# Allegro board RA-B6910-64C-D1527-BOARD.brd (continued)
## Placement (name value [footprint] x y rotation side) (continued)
R573  3.3K_1%  [R0402]  135.05 135.31 0 bottom
R574  X  [R0402]  161.21 109.25 180 top
R575  3.3K_1%  [R0402]  161.21 108.23 0 top
R576  X  [R0402]  157.4 105.84 90 top
R577  3.3K_1%  [R0402]  158.42 105.84 270 top
R578  3.3K_1%  [R0402]  152.07 105.84 90 bottom
R579  X  [R0402]  153.08 105.84 270 bottom
R580  X  [R0402]  161.21 118.16 180 top
R581  3.3K_1%  [R0402]  150.03 105.84 90 bottom
R582  X  [R0402]  149.02 105.84 270 bottom
R583  X  [R0402]  133.9 130.99 0 bottom
R584  3.3K_1%  [R0402]  154.35 105.84 90 top
R585  X  [R0402]  155.37 105.84 270 top
R586  3.3K_1%  [R0402]  146.99 105.84 90 bottom
R587  X  [R0402]  145.97 105.84 270 bottom
R588  3.3K_1%  [R0402]  161.21 110.26 180 top
R589  X  [R0402]  161.21 111.28 0 top
R590  X  [R0402]  158.67 108.51 180 bottom
R591  3.3K_1%  [R0402]  158.67 109.53 0 bottom
R592  0  [R0402]  155.11 108.76 270 bottom
R593  X  [R0402]  154.1 108.76 90 bottom
R594  X  [R0402]  176.96 106.86 90 bottom
R595  10K_1%  [R0402]  169.85 106.86 270 bottom
R596  0  [R0402]  175.94 106.86 270 bottom
R597  10K_1%  [R0402]  167.81 106.86 270 bottom
R598  10K_1%  [R0402]  172.89 106.86 90 bottom
R599  10K_1%  [R0402]  174.93 106.86 270 bottom
R600  100K_1%  [R0402]  164.77 106.86 270 top
R601  100K_1%  [R0402]  158.67 110.54 180 bottom
R602  X  [R0402]  158.67 111.56 0 bottom
R603  X  [R0402]  176.45 109.4 180 bottom
R604  X  [R0402]  176.45 110.41 180 bottom
R605  X  [R0402]  173.27 111.18 0 top
R606  X  [R0402]  172.64 113.21 270 top
R607  3.3K_1%  [R0402]  165.15 88.06 0 top
R608  3.3K_1%  [R0402]  154.48 87.05 0 top
R609  X  [R0402]  154.48 88.06 0 top
R610  15K_1%  [R0402]  165.15 87.05 0 top
R611  1.5K_1%  [R0402]  165.15 86.03 0 top
R612  33_1%  [R0402]  173.91 106.86 90 bottom
R613  33_1%  [R0402]  170.86 106.86 90 bottom
R614  33_1%  [R0402]  168.83 106.86 90 bottom
R615  22  [R0402]  170.35 121.34 270 top
R616  33  [R0402]  163.75 106.86 270 bottom
R617  4.99K_1%  [R0402]  172.64 121.34 270 bottom
R618  33  [R0402]  164.77 106.86 270 bottom
R619  33  [R0402]  165.78 106.86 270 bottom
R620  33  [R0402]  166.8 106.86 270 bottom
R621  3.3K_1%  [R0402]  171.88 106.86 270 bottom
R622  3.3K_1%  [R0402]  164.89 115.62 0 top
R623  3.3K_1%  [R0402]  164.77 110.67 0 top
R624  3.3K_1%  [R0402]  164.77 109.65 0 top
R625  3.3K_1%  [R0402]  168.96 121.34 90 bottom
R626  3.3K_1%  [R0402]  169.97 121.34 90 bottom
R627  10K_1%  [R0402]  164.89 114.48 0 top
R628  4.7K  [R0402]  176.45 108.38 0 bottom
R629  0  [R0603]  159.81 118.29 180 bottom
R630  3.09K_1%  [R0402]  161.21 114.61 0 top
R631  49.9K_1%  [R0603]  161.59 116.89 180 top
R632  15K_1%  [R0402]  161.21 115.62 180 top
R641  0  [R0402]  117.01 26.47 0 top
R642  3.3  [R0402]  127.43 19.86 0 top
R643  0  [R0402]  127.43 20.88 0 top
R644  1_1%  [R0402]  127.43 20.88 0 bottom
R645  499K_1%  [R0603]  116.63 23.42 270 top
R646  150K_1%  [R0603]  117.01 16.18 270 top
R647  0  [R0402]  118.28 16.31 270 top
R648  0  [R0402]  119.43 16.31 270 top
R649  12.7K_1%  [R0603]  120.82 12.75 90 top
R650  1_1%  [R0402]  123.11 13.89 90 top
R651  10K_1%  [R0402]  127.43 21.9 0 bottom
R652  10K_1%  [R0402]  119.55 13.13 90 top
R653  10K_1%  [R0402]  127.43 27.61 0 top
R654  10K_1%  [R0402]  124.38 13.89 270 top
R656  0  [R0402]  127.43 26.59 0 top
R657  200_1%  [R0402]  127.43 18.85 180 top
R658  0  [R0402]  127.43 22.91 0 top
R659  0  [R0402]  127.43 24.18 0 top
R660  0  [R0402]  127.43 25.32 0 top
R662  40.2_1%  [R0402]  66.34 17.83 180 bottom
R663  X  [R0402]  66.34 19.86 0 bottom
R664  120_1%  [R0402]  66.34 18.85 180 bottom
R665  2  [R0603]  113.2 23.83 270 top
R666  0  [R0402]  111.04 13.26 270 top
R667  1  [R0805]  105.08 16.23 270 top
R668  150K_1%  [R0603]  114.6 23.83 270 top
R669  0  [R0402]  115.11 13.26 270 top
R670  0  [R0402]  113.08 13.26 90 top
R671  X  [R0402]  114.09 13.26 270 top
R672  2  [R0603]  102.15 23.55 270 top
R673  0  [R0402]  99.61 13.26 270 top
R674  1  [R0805]  93.01 16.99 270 top
R675  150K_1%  [R0603]  103.55 23.55 270 top
R676  0  [R0402]  103.17 13.26 270 top
R677  0  [R0402]  101.65 13.26 90 top
R678  1  [R0805]  127.43 15.29 0 top
R679  0  [R0402]  133.4 13.77 270 top
R680  2  [R0603]  138.1 14.66 270 top
R681  150K_1%  [R0603]  135.17 21.51 0 bottom
R682  0  [R0402]  134.41 13.77 90 top
R683  X  [R0402]  135.43 13.77 90 top
R684  0  [R0402]  136.44 13.77 270 top
R685  0  [R0402]  162.99 38.28 180 top
R686  0  [R0402]  162.99 33.71 180 top
R687  3.3  [R0402]  174.29 32.44 0 top
R688  0  [R0402]  174.29 33.45 0 top
R689  1_1%  [R0402]  174.29 35.48 0 top
R690  X  [R0402]  162.99 32.69 0 top
R691  49.9K_1%  [R0603]  162.99 31.42 0 top
R692  20K_1%  [R0603]  162.99 30.02 180 top
R693  0  [R0402]  165.15 29.9 270 top
R694  0  [R0402]  166.67 29.9 270 top
R695  12.7K_1%  [R0603]  168.07 26.34 90 top
R696  1_1%  [R0402]  170.48 27.48 90 top
R697  10K_1%  [R0402]  174.29 35.48 0 bottom
R698  10K_1%  [R0402]  166.67 26.72 90 top
R699  X  [R0402]  174.29 40.69 0 top
R700  10K_1%  [R0402]  172.77 29.9 270 top
R702  200_1%  [R0402]  174.29 31.42 180 top
R703  0  [R0402]  174.29 39.68 0 top
R704  0  [R0402]  174.29 36.5 0 top
R705  0  [R0402]  174.29 37.52 0 top
R706  0  [R0402]  174.29 38.66 0 top
R708  1  [R0805]  154.48 36.37 0 top
R709  0  [R0402]  159.3 40.18 0 top
R710  2  [R0603]  153.97 34.47 0 bottom
R711  150K_1%  [R0603]  151.43 45.01 90 bottom
R712  0  [R0402]  159.3 42.22 180 bottom
R713  X  [R0402]  159.3 42.22 180 top
R714  0  [R0402]  159.3 43.87 0 top
R715  1  [R0805]  154.35 45.85 0 top
R716  0  [R0402]  161.34 49.96 0 top
R717  2  [R0603]  146.1 53.01 180 bottom
R718  150K_1%  [R0603]  152.45 49.45 270 bottom
R719  0  [R0402]  159.18 51.11 180 top
R720  X  [R0402]  159.18 52.12 180 top
R721  0  [R0402]  159.18 53.14 0 top
R722  0  [R0402]  56.05 25.96 180 top
R723  3.3  [R0402]  66.34 18.85 0 top
R724  0  [R0402]  66.34 19.86 0 top
R725  1_1%  [R0402]  66.34 21.9 0 top
R726  0  [R0402]  55.67 20.37 0 top
R727  27K_1%  [R0402]  55.67 18.09 0 top
R728  X  [R0402]  55.67 19.1 0 top
R729  37.4K_1%  [R0603]  55.29 16.69 180 top
R730  0  [R0402]  57.32 16.82 270 top
R731  0  [R0402]  58.47 16.82 270 top
R732  12.7K_1%  [R0603]  59.74 15.93 90 bottom
R733  1_1%  [R0402]  62.02 13.89 90 top
R734  10K_1%  [R0402]  66.34 21.9 0 bottom
R735  10K_1%  [R0402]  58.47 14.28 90 top
R736  X  [R0402]  66.34 27.36 0 top
R737  10K_1%  [R0402]  64.56 13.89 270 top
R739  0  [R0402]  66.34 26.34 0 top
R740  200_1%  [R0402]  66.34 17.83 180 top
R741  0  [R0402]  66.34 22.91 0 top
R742  0  [R0402]  66.34 24.18 0 top
R743  0  [R0402]  66.34 25.32 0 top
R745  2  [R0603]  90.09 23.55 270 top
R746  0  [R0402]  87.04 13.26 270 top
R748  1  [R0805]  80.82 16.36 270 top
R749  150K_1%  [R0603]  91.49 23.55 270 top
R750  0  [R0402]  91.11 13.26 270 top
R751  0  [R0402]  89.07 13.26 90 top
R752  X  [R0402]  90.09 13.26 270 top
R753  1  [R0805]  70.53 21.13 270 top
R754  0  [R0402]  74.85 13.77 270 top
R755  2  [R0603]  78.66 23.04 90 top
R756  150K_1%  [R0603]  80.06 23.04 90 top
R757  0  [R0402]  76.88 13.77 90 top
R758  X  [R0402]  77.9 13.77 90 top
R759  0  [R0402]  78.91 13.77 270 top
R760  4.7K  [R0402]  117.65 136.07 0 top
R761  4.7K  [R0402]  113.33 127.56 270 bottom
R762  4.7K  [R0402]  102.41 132.77 180 top
R763  33  [R0402]  112.31 127.56 90 bottom
R764  X  [R0402]  110.28 127.56 270 bottom
R765  33  [R0402]  117.65 134.04 180 top
R766  33  [R0402]  102.41 131.75 180 top
R767  33  [R0402]  117.65 135.05 180 top
R768  33  [R0402]  102.41 134.8 180 top
R769  33  [R0402]  102.41 135.81 180 top
R770  4.7K  [R0402]  117.27 145.47 0 top
R771  4.7K  [R0402]  117.27 143.43 0 top
R772  4.7K  [R0402]  101.9 144.45 180 top
R773  33  [R0402]  117.27 142.42 180 top
R774  33  [R0402]  117.27 144.45 180 top
R775  X  [R0402]  101.9 141.4 0 top
R776  33  [R0402]  101.9 143.43 180 top
R777  33  [R0402]  117.27 146.48 180 top
R778  33  [R0402]  101.9 145.72 180 top
R779  33  [R0402]  101.9 146.74 180 top
R780  X  [R0402]  105.46 54.66 90 top
R781  49.9_1%  [R0402]  113.71 58.6 180 top
R782  1K_1%  [R0402]  103.68 71.43 180 bottom
R783  X  [R0402]  113.71 61.65 180 top
R784  5.11K_1%  [R0402]  106.47 54.66 90 top
R785  5.11K_1%  [R0402]  104.44 54.66 90 top
R786  5.11K_1%  [R0402]  104.44 54.66 90 bottom
R787  5.11K_1%  [R0402]  99.87 66.29 0 bottom
R788  10  [R0402]  94.03 57.07 90 bottom
R789  10  [R0402]  94.79 54.66 90 top
R790  X  [R0402]  110.54 54.66 90 top
R791  10  [R0402]  95.8 54.66 90 top
R792  10K_1%  [R0402]  107.49 54.66 90 top
R793  10K_1%  [R0402]  108.5 54.66 90 top
R794  10K_1%  [R0402]  98.98 63.68 180 bottom
R795  5.11K_1%  [R0402]  102.41 54.66 90 top
R796  5.11K_1%  [R0402]  109.52 54.66 90 bottom
R797  5.11K_1%  [R0402]  108.5 54.66 90 bottom
R798  5.11K_1%  [R0402]  113.71 56.57 180 top
R799  5.11K_1%  [R0402]  111.55 54.66 90 bottom
R800  X  [R0402]  111.55 57.07 90 bottom
R801  X  [R0402]  113.71 57.58 180 top
R802  4.7K  [R0402]  150.8 65.71 90 bottom
R803  33  [R0402]  149.78 65.71 90 bottom
R804  33  [R0402]  148.76 65.71 90 bottom
R805  4.7K  [R0402]  149.78 76.38 90 bottom
R806  4.7K  [R0402]  147.75 65.71 90 bottom
R807  33  [R0402]  144.95 76.12 180 bottom
R808  33  [R0402]  144.95 75.11 180 bottom
R809  7.5K  [R0603]  86.89 84.51 90 bottom
R810  22.6_1%  [R0603]  104.31 114.1 0 top
R811  0  [R0402]  103.81 110.54 0 top
R812  0  [R0402]  103.81 109.53 0 top
R813  0  [R0402]  103.81 105.46 0 bottom
R814  0  [R0402]  103.81 115.62 0 top
R815  0  [R0402]  102.15 103.81 90 top
R816  5.11K_1%  [R0402]  81.45 108.76 270 top
R817  5.11K_1%  [R0402]  82.47 105.59 270 bottom
R818  5.11K_1%  [R0402]  92.63 116.26 270 top
R819  5.11K_1%  [R0402]  103.81 108.51 180 top
R820  X  [R0402]  82.34 116.13 270 top
R821  5.11K_1%  [R0402]  84.5 105.59 270 bottom
R822  5.11K_1%  [R0402]  86.53 111.18 270 bottom
R823  5.11K_1%  [R0402]  84.5 111.18 270 bottom
R824  5.11K_1%  [R0402]  105.84 105.97 180 bottom
R825  X  [R0402]  103.81 116.64 0 top
R826  X  [R0402]  103.17 104.95 270 top
R827  5.11K_1%  [R0402]  103.81 108.51 180 bottom
R828  X  [R0402]  114.09 71.93 0 bottom
R829  0  [R0402]  81.45 108.76 270 bottom
R830  5.11K_1%  [R0402]  91.36 82.22 90 bottom
R831  5.11K_1%  [R0402]  89.33 82.22 90 bottom
R832  5.11K_1%  [R0402]  90.6 112.95 270 top
R833  5.11K_1%  [R0402]  88.57 112.95 270 top
R834  5.11K_1%  [R0402]  90.34 82.22 90 bottom
R835  49.9_1%  [R0402]  102.92 56.57 180 top
R836  5.11K_1%  [R0402]  103.81 111.56 180 bottom
R837  X  [R0402]  103.42 54.66 90 bottom
R838  5.11K_1%  [R0402]  103.81 109.53 180 bottom
R839  33  [R0402]  82.98 112.95 270 bottom
R840  2.2K  [R0402]  93.14 81.71 180 bottom
R841  0  [R0402]  91.61 112.95 90 top
R842  5.11K_1%  [R0402]  78.79 108.76 270 bottom
R843  5.11K_1%  [R0402]  100.38 54.66 90 top
R844  5.11K_1%  [R0402]  79.8 108.76 90 bottom
R845  5.11K_1%  [R0402]  103.42 54.66 90 top
R846  7.5K  [R0603]  100.76 90.35 0 bottom
R847  5.11K_1%  [R0402]  80.44 112.95 270 bottom
R848  5.11K_1%  [R0402]  81.2 116.13 270 top
R849  33  [R0402]  113.71 54.53 0 top
R850  5.11K_1%  [R0402]  81.45 112.95 270 bottom
R851  5.11K_1%  [R0402]  81.45 105.59 270 bottom
R852  33  [R0402]  91.99 116.38 90 bottom
R853  33  [R0402]  94.03 116.38 90 bottom
R854  5.11K_1%  [R0402]  91.61 116.26 270 top
R855  5.11K_1%  [R0402]  89.58 112.95 270 top
R856  5.11K_1%  [R0402]  84.25 113.59 270 bottom
R857  5.11K_1%  [R0402]  103.81 107.49 180 bottom
R858  5.11K_1%  [R0402]  83.49 116.13 270 top
R859  5.11K_1%  [R0402]  82.47 112.95 270 top
R860  X  [R0402]  141.27 112.19 0 bottom
R861  5.11K_1%  [R0402]  89.58 112.95 270 bottom
R862  10K_1%  [R0402]  102.66 89.08 180 bottom
R863  0  [R0402]  136.95 111.56 180 bottom
R864  5.11K_1%  [R0402]  84.5 105.59 270 top
R865  5.11K_1%  [R0402]  83.49 105.59 270 top
R866  X  [R0402]  80.44 112.95 270 top
R867  X  [R0402]  138.48 108.26 0 bottom
R868  1K  [R0402]  103.81 113.97 180 bottom
R869  0  [R0402]  136.32 108.26 180 bottom
R870  5.11K_1%  [R0402]  88.95 116.26 270 bottom
R871  1K  [R0402]  91.99 108.76 270 top
R872  X  [R0402]  139.11 112.95 0 bottom
R873  10K_1%  [R0402]  93.77 108.76 270 bottom
R874  5.11K_1%  [R0402]  103.81 110.54 180 bottom
R875  0  [R0402]  136.95 112.95 180 bottom
R876  5.11K_1%  [R0402]  92.63 105.59 270 top
R877  5.11K_1%  [R0402]  90.6 112.95 270 bottom
R878  X  [R0402]  138.48 109.65 0 bottom
R879  10K_1%  [R0402]  90.6 108.76 270 bottom
R880  5.11K_1%  [R0402]  103.81 112.88 180 bottom
R881  0  [R0402]  136.32 109.65 180 bottom
R882  5.11K_1%  [R0402]  91.61 108.76 270 bottom
R883  10K_1%  [R0402]  87.55 108.76 270 bottom
R884  5.11K_1%  [R0402]  85.52 108.76 270 bottom
R885  5.11K_1%  [R0402]  84.5 108.76 270 bottom
R886  5.11K_1%  [R0402]  93.01 116.38 270 bottom
R887  X  [R0402]  86.53 108.76 90 bottom
R888  1K  [R0402]  93.77 108.76 270 top
R889  X  [R0402]  83.49 108.76 90 bottom
R890  1M_1%  [R0603]  104.44 105.46 270 top
R891  5.11K_1%  [R0402]  103.81 111.56 180 top
R892  5.11K_1%  [R0402]  103.81 107.49 180 top
R893  2.2K  [R0402]  95.68 119.56 90 top
R894  1M_1%  [R0603]  97.58 105.59 180 top
R895  5.11K_1%  [R0402]  85.26 83.11 90 bottom
R896  5.11K_1%  [R0402]  103.42 57.07 90 bottom
R897  1K  [R0402]  96.69 119.56 270 top
R898  5.11K_1%  [R0402]  79.68 115.25 270 top
R899  5.11K_1%  [R0402]  93.77 112.95 270 bottom
R900  5.11K_1%  [R0402]  94.28 96.44 270 bottom
R901  5.11K_1%  [R0402]  81.33 97.21 270 bottom
R902  X  [R0402]  101.39 54.66 90 top
R903  X  [R0402]  81.45 112.95 270 top
R904  X  [R0402]  89.96 116.26 270 bottom
R905  0  [R0402]  116.63 55.55 0 top
R906  X  [R0402]  116.63 54.53 0 top
R907  X  [R0402]  101.39 54.66 90 bottom
R908  49.9_1%  [R0402]  97.33 54.66 270 bottom
R909  X  [R0402]  99.36 54.66 90 bottom
R910  120_1%  [R0402]  98.34 54.66 90 bottom
R911  5.11K_1%  [R0402]  92.25 69.27 270 bottom
R912  5.11K_1%  [R0402]  93.26 69.27 270 bottom
R913  5.11K_1%  [R0402]  96.31 54.66 90 bottom
R914  240_1%  [R0402]  91.36 67.23 270 bottom
R915  240_1%  [R0402]  95.04 57.07 90 bottom
R916  0  [R0402]  98.34 57.07 270 bottom
R917  1K  [R0402]  100.38 54.66 90 bottom
R918  220_1%  [R0402]  97.33 57.07 270 bottom
R919  0  [R0402]  99.36 57.07 270 bottom
R920  5.11K_1%  [R0402]  100.88 57.07 90 bottom
R921  5.11K_1%  [R0402]  106.99 63.04 180 bottom
R922  5.11K_1%  [R0402]  97.33 54.66 90 top
R923  10K_1%  [R0402]  97.33 79.18 270 bottom
R924  10K_1%  [R0402]  96.19 79.18 270 bottom
R925  10K_1%  [R0402]  104.19 102.29 0 top
R926  150_1%  [R0402]  113.71 64.69 180 top
R927  10K_1%  [R0402]  107.36 80.95 0 bottom
R928  10K_1%  [R0402]  107.36 81.97 0 bottom
R929  10K_1%  [R0402]  104.19 103.3 0 top
R930  75_1%  [R0402]  113.71 63.68 0 top
R931  10K_1%  [R0402]  88.31 82.22 270 bottom
R932  10K_1%  [R0402]  87.3 81.46 270 bottom
R933  10K_1%  [R0402]  105.08 91.87 0 bottom
R934  0  [R0402]  107.87 115.75 0 top
R935  0  [R0402]  103.81 115.62 0 bottom
R936  5.11K_1%  [R0402]  107.87 114.73 0 top
R937  5.11K_1%  [R0402]  103.81 116.64 0 bottom
R938  22  [R0402]  100.5 101.78 0 bottom
R939  1M_1%  [R0603]  108 103.18 0 top
R940  33  [R0402]  118.03 125.53 180 top
R941  4.7K  [R0402]  118.03 126.8 0 top
R942  33  [R0402]  129.21 126.54 0 top
R943  33  [R0402]  129.21 127.56 0 top
R944  33  [R0402]  129.21 128.58 0 top
R945  5.11K_1%  [R0402]  85.52 105.59 270 bottom
R946  5.11K_1%  [R0402]  94.03 57.07 270 top
R947  5.11K_1%  [R0402]  114.09 73.97 0 top
R948  5.11K_1%  [R0402]  113.71 59.61 0 top
R949  5.11K_1%  [R0402]  113.71 60.63 0 top
R950  5.11K_1%  [R0402]  97.71 69.9 90 bottom
R951  5.11K_1%  [R0402]  95.8 69.01 90 bottom
R952  5.11K_1%  [R0402]  94.79 69.01 90 bottom
R953  5.11K_1%  [R0402]  113.71 62.66 0 top
R954  49.9_1%  [R0402]  98.73 70.79 90 bottom
R955  5.11K_1%  [R0402]  114.09 71.93 0 top
R956  5.11K_1%  [R0402]  114.09 72.95 0 top
R957  X  [R0402]  91.87 63.55 0 bottom
R958  5.11K_1%  [R0402]  103.81 112.88 180 top
R959  7.50K_1%  [R0805]  102.03 81.59 270 bottom
R960  8.2K  [R0402]  105.13 92.89 0 bottom
R961  49.9_1%  [R0402]  113.71 55.55 180 top
R962  49.9_1%  [R0402]  100 62.54 180 bottom
R963  10K_1%  [R0402]  106.47 54.66 270 bottom
R964  49.9_1%  [R0402]  74.72 62.79 270 bottom
R965  10K_1%  [R0402]  105.46 54.66 270 bottom
R966  49.9_1%  [R0402]  73.2 62.79 90 bottom
R967  130_1%  [R0603]  81.71 72.82 90 bottom
R968  40.2_1%  [R0402]  80.95 74.85 180 bottom
R969  120_1%  [R0402]  81.45 77.39 0 bottom
R970  1_1%  [R0402]  81.45 75.87 180 bottom
R971  7.5K  [R0603]  101.27 85.27 0 bottom
R972  10K_1%  [R0402]  83.49 108.76 270 top
R973  0  [R0402]  88.57 105.59 270 top
R974  10K_1%  [R0402]  85.52 108.76 270 top
R975  5.11K_1%  [R0402]  84.5 108.76 270 top
R976  1K  [R0402]  86.53 108.76 270 top
R977  5.11K_1%  [R0402]  82.47 105.59 270 top
R978  5.11K_1%  [R0402]  82.47 108.76 270 top
R979  1K  [R0402]  87.55 113 270 bottom
R980  1K  [R0402]  88.57 112.95 270 bottom
R981  1K  [R0402]  89.58 105.59 270 bottom
R982  X  [R0402]  87.93 108.76 270 top
R983  10K_1%  [R0402]  89.96 108.76 270 top
R984  10K_1%  [R0402]  89.58 105.59 270 top
R985  1K_1%  [R0402]  57.96 68.12 270 bottom
R986  10K_1%  [R0402]  87.55 113 270 top
R987  10K_1%  [R0402]  91.61 105.59 270 top
R988  10K_1%  [R0402]  88.95 108.76 270 top
R989  10K_1%  [R0402]  90.6 105.59 270 top
R990  10K_1%  [R0402]  90.98 108.76 270 top
R991  0  [R0402]  59.74 66.47 180 bottom
R992  49.9_1%  [R0402]  86.15 112.95 90 top
R993  1K_1%  [R0402]  59.74 67.62 0 bottom
R994  49.9_1%  [R0402]  86.53 105.59 90 top
R995  49.9_1%  [R0402]  87.55 105.59 90 top
R996  49.9_1%  [R0402]  85.52 105.59 90 top
R997  X  [R0402]  107.11 117.4 180 bottom
R998  4.7K  [R0402]  107.11 120.45 180 bottom
R999  4.7K  [R0402]  107.11 121.46 180 bottom
R1000  4.7K  [R0402]  99.49 118.92 180 top
R1001  4.7K  [R0402]  107.11 118.42 180 bottom
R1002  X  [R0402]  107.11 119.43 180 bottom
R1003  0  [R0402]  99.49 119.94 180 top
R1004  X  [R0402]  107.11 122.48 180 bottom
R1005  33  [R0402]  99.49 121.97 180 top
R1006  33  [R0402]  99.49 122.99 180 top
R1007  X  [R0402]  99.49 120.96 0 top
R1008  0  [R1206]  112.19 83.62 0 bottom
R1018  49.9_1%  [R0402]  109.27 57.58 180 top
R1019  49.9_1%  [R0402]  109.52 54.66 90 top
R1020  49.9_1%  [R0402]  111.55 54.66 90 top
R1023  931_1%  [R0402]  105.72 59.87 180 bottom
R1025  49.9_1%  [R0402]  103.3 63.55 180 bottom
R1028  1K  [R0402]  74.09 125.65 270 top
R1029  150  [R0402]  102.66 59.99 90 bottom
R1030  1K  [R0402]  101.9 140.39 0 top
R1031  1K  [R0402]  111.17 107.11 0 bottom
R1032  1K  [R0402]  102.41 133.78 0 top
R1033  1K  [R0402]  113.97 139.5 0 bottom
R1034  1K  [R0402]  113.97 140.51 0 bottom
R1035  1K  [R0402]  99.36 54.66 270 top
R1036  1K  [R0402]  122.86 111.18 0 bottom
R1037  240_1%  [R0402]  113.84 136.07 0 bottom
R1039  49.9_1%  [R0402]  113.84 130.99 0 bottom
R1040  0  [R0402]  113.97 138.48 180 bottom
R1041  0  [R0402]  122.86 110.16 180 bottom
R1042  0  [R0402]  122.86 106.1 180 bottom
R1043  0  [R0402]  113.97 141.53 180 bottom
R1045  0  [R0402]  122.86 109.14 180 bottom
R1046  0  [R0402]  113.97 142.55 180 bottom
R1047  0  [R0402]  113.84 134.04 180 bottom
R1048  X  [R0402]  113.97 144.58 180 bottom
R1049  0  [R0402]  113.84 135.05 180 bottom
R1050  0  [R0402]  113.84 132 180 bottom
R1051  1K  [R0402]  113.97 143.56 180 bottom
R1052  1K  [R0402]  122.86 107.11 180 bottom
R1053  4.7K  [R0402]  122.86 108.13 0 bottom
R1054  240_1%  [R0402]  122.86 104.06 0 top
R1055  240_1%  [R0402]  122.86 100 0 top
R1056  X  [R0402]  122.73 97.71 0 top
R1057  1K  [R0402]  111.17 109.91 0 top
R1058  240_1%  [R0402]  122.86 101.02 0 top
R1059  0  [R0402]  122.86 103.05 180 top
R1060  0  [R0402]  122.86 102.03 180 top
R1061  0  [R0402]  122.86 98.73 180 top
R1062  0  [R0402]  122.73 96.7 180 top
R1063  49.9_1%  [R0402]  122.86 105.08 0 top
R1064  0  [R0402]  122.86 109.14 180 top
R1065  1K  [R0402]  111.17 102.54 0 top
R1066  1K  [R0402]  134.41 66.85 0 top
R1068  0  [R0402]  125.78 70.79 180 top
R1069  0  [R0402]  125.78 72.82 180 top
R1070  0  [R0402]  122.86 108.13 180 top
R1071  0  [R0402]  122.86 106.1 180 top
R1072  1K  [R0402]  125.78 69.77 180 top
R1073  1K  [R0402]  125.78 71.81 180 top
R1074  1K  [R0402]  125.78 73.84 180 top
R1075  1K  [R0402]  125.78 74.85 180 top
R1076  5.11K_1%  [R0402]  98.34 54.66 90 top
R1077  5.11K_1%  [R0402]  122.86 110.16 180 top
R1078  1K  [R0402]  122.86 107.11 180 top
R1079  X  [R0402]  125.78 70.79 0 bottom
R1080  X  [R0402]  125.78 72.82 0 bottom
R1081  1K  [R0402]  137.33 70.16 180 bottom
R1082  1K  [R0402]  137.33 71.17 180 bottom
R1083  X  [R0402]  125.78 73.84 180 bottom
R1084  200K  [R0603]  137.71 68.89 0 bottom
R1085  X  [R0402]  125.78 71.81 180 bottom
R1086  X  [R0402]  125.78 74.85 180 bottom
R1087  10K_1%  [R0402]  137.33 72.19 0 bottom
R1088  10  [R0402]  137.33 73.2 0 bottom
R1089  10  [R0402]  137.33 75.24 0 bottom
R1090  10  [R0402]  137.33 74.22 0 bottom
R1091  240_1%  [R0402]  74.34 38.66 180 top
R1092  240_1%  [R0402]  74.34 37.52 180 top
R1093  4.7K  [R0402]  64.18 36.12 0 top
R1094  4.7K  [R0402]  64.18 37.14 0 top
R1095  10K_1%  [R0402]  64.18 38.15 0 top
R1096  1K  [R0402]  125.01 65.71 270 top
R1097  4.7K  [R0402]  137.46 105.33 180 top
R1098  4.7K  [R0402]  137.46 104.32 180 top
R1099  240_1%  [R0402]  126.28 103.81 0 top
R1100  240_1%  [R0402]  126.28 104.83 0 top
R1101  240_1%  [R0402]  129.08 110.41 90 top
R1102  240_1%  [R0402]  128.06 110.41 90 top
R1103  10K_1%  [R0402]  128.95 122.1 270 top
R1104  10K_1%  [R0402]  137.46 103.3 180 top
R1105  1K  [R0402]  145.21 65.71 270 top
R1106  1K  [R0402]  145.21 77.39 270 top
R1107  0  [R0402]  144.19 65.71 90 top
R1108  1K  [R0402]  152.19 76.38 270 bottom
R1109  0  [R0402]  143.18 65.71 90 top
R1110  0  [R0402]  142.16 65.71 90 top
R1111  33  [R0402]  148.76 65.71 90 top
R1112  0  [R0402]  150.8 65.71 90 top
R1113  1K  [R0402]  147.75 65.71 90 top
R1114  1K  [R0402]  149.78 65.71 90 top
R1115  0  [R0402]  122.09 16.31 90 top
R1116  X  [R0402]  18.21 41.07 270 bottom
R1118  X  [R0402]  19.35 41.07 270 bottom
R1120  X  [R0402]  10.21 71.68 90 bottom
R1122  X  [R0402]  25.83 50.47 180 bottom
R1123  0  [R0402]  22.91 47.93 90 bottom
R1125  0  [R0402]  24.3 67.23 180 bottom
R1129  0  [R0402]  122.22 113.97 180 top
R1130  0  [R0402]  122.22 114.99 180 top
R1131  0  [R0402]  91.23 133.02 0 bottom
R1132  0  [R0402]  125.01 110.41 90 bottom
R1133  0  [R0402]  124.76 121.08 180 top
R1134  X  [R0402]  96.31 57.07 90 bottom
R1135  X  [R0402]  84.37 147.5 90 bottom
R1136  X  [R0402]  85.39 147.5 90 bottom
R1137  240_1%  [R0402]  113.84 133.02 0 bottom
R1138  0  [R0402]  171.5 121.34 90 top
R1139  100  [R0402]  89.45 150.04 270 bottom
R1140  100  [R0402]  88.44 150.04 270 bottom
R1141  100  [R0402]  87.42 150.04 270 bottom
R1142  33  [R0402]  85.14 150.55 180 bottom
R1143  4.7K  [R0402]  81.96 153.59 90 bottom
R1144  4.7K  [R0402]  80.95 153.59 270 bottom
R1145  4.7K  [R0402]  89.2 161.72 270 bottom
R1146  4.7K  [R0402]  90.22 161.72 90 bottom
R1157  4.7K  [R0402]  126.28 110.41 90 bottom
R1158  4.7K  [R0402]  124.76 119.05 180 top
R1159  4.7K  [R0402]  124.76 118.03 0 top
R1160  4.7K  [R0402]  124.51 114.99 0 top
R1161  4.7K  [R0402]  124.51 113.97 180 top
R1162  4.7K  [R0402]  124.76 120.07 180 top
R1163  0  [R0402]  89.58 116.26 90 top
R1164  5.11K_1%  [R0402]  90.6 116.26 270 top
R1165  10K_1%  [R0402]  106.35 56.57 180 top
R1166  X  [R0603]  89.58 138.99 90 bottom
R1167  33  [R0402]  85.14 161.72 90 bottom
R1168  33  [R0402]  86.15 161.72 90 bottom
R1169  33  [R0402]  87.17 161.72 90 bottom
R1170  33  [R0402]  88.18 161.72 90 bottom
R1172  10K_1%  [R0402]  78.66 157.53 0 bottom
R1173  10K_1%  [R0402]  82.09 161.34 0 bottom
R1174  5.11K_1%  [R0402]  83.49 112.95 270 top
R1175  10K_1%  [R0402]  95.55 148.64 270 bottom
R1176  10K_1%  [R0402]  93.77 154.36 0 bottom
R1177  X  [R0402]  99.87 68.5 0 bottom
R1178  X  [R0402]  104.44 57.07 90 bottom
R1179  X  [R0402]  102.41 54.66 90 bottom
R1180  X  [R0402]  94.28 94.41 90 bottom
R1181  X  [R0402]  110.54 54.66 90 bottom
R1182  X  [R0402]  79.42 112.95 270 top
R1183  X  [R0402]  86.53 105.59 270 bottom
R1184  4.7K  [R0402]  59.48 141.28 180 top
R1185  33_1%  [R0402]  69.64 144.45 270 top
R1186  4.7K  [R0402]  94.28 142.29 0 top
R1187  4.7K  [R0402]  94.28 144.45 0 top
R1188  33  [R0402]  94.28 140.77 0 top
R1189  33  [R0402]  94.28 145.47 0 top
R1190  X  [R0402]  182.92 88.19 0 top
R1191  X  [R0402]  182.92 87.17 0 top
R1192  X  [R0603]  123.22 146.61 270 bottom
R1193  300  [R0603]  119.55 148.9 90 top
R1194  300  [R0603]  118.03 148.9 90 top
R1195  10  [R0402]  119.3 155.88 0 top
R1196  X  [R0603]  82.99 121.97 270 top
R1197  300  [R0603]  77.01 121.32 180 top
R1198  300  [R0603]  77.01 122.85 180 top
R1199  10  [R0402]  76.38 115.24 180 top
R1200  1K_1%  [R0402]  65.97 29.9 180 top
R1202  0  [R0402]  155.88 119.43 180 bottom
R1203  0  [R0402]  155.88 121.84 180 bottom
R1204  0  [R0402]  136.32 139.88 270 bottom
R1205  0  [R0402]  135.3 139.88 270 bottom
R1206  X  [R0402]  84.24 98.22 0 bottom
R1207  33  [R0402]  91.23 132 0 bottom
R1208  33  [R0402]  94.28 130.86 0 bottom
R1209  0  [R0402]  164.77 13.51 180 top
R1210  4.7K  [R0402]  188.39 16.18 270 top
R1211  X  [R0402]  187.12 16.18 90 top
R1212  X  [R0402]  189.66 16.18 90 top
R1213  75K_1%  [R0603]  185.47 19.23 270 top
R1214  22K_1%  [R0805]  188.39 18.85 0 top
R1215  X  [R0603]  188.64 4.37 270 top
R1216  0  [R0402]  71.17 141.28 0 bottom
R1217  14.7K_1%  [R0402]  57.7 127.56 90 top
R1218  4.99K_1%  [R0402]  59.36 126.8 0 top
R1219  4.7K  [R0402]  56.56 127.56 90 top
R1220  4.7K  [R0402]  57.07 137.47 0 top
R1221  1K  [R0402]  59.48 137.47 0 top
R1222  1K  [R0402]  55.29 135.18 90 top
R1230  0  [R0402]  59.36 128.07 180 top
R1231  1K  [R0402]  109.01 161.47 0 bottom
R1232  12K_1%  [R0603]  98.98 160.83 270 top
R1233  X  [R0603]  100.38 160.83 270 top
R1234  15K_1%  [R0402]  96.44 159.56 90 top
R1235  4.7K  [R0402]  117.65 161.72 0 top
R1236  1.21K_1%  [R0805]  116.89 159.69 180 top
R1237  X  [R0603]  114.98 161.72 0 top
R1238  1K_1%  [R0603]  113.97 159.31 270 top
R1239  X  [R0402]  50.08 134.8 270 top
R1240  100_1%  [R0402]  45.77 139.5 90 bottom
R1241  3.01K_1%  [R0603]  47.93 127.05 270 top
R1242  3.01K_1%  [R0603]  50.72 127.05 270 top
R1243  3.01K_1%  [R0603]  49.32 127.05 270 top
R1244  47.5K_1%  [R0603]  53.01 135.18 90 top
R1245  10K_1%  [R0402]  46.91 139.5 90 bottom
R1246  4.7K  [R0402]  48.05 139.5 270 bottom
R1247  3.01K_1%  [R0603]  45.51 127.81 0 top
R1248  6.81K_1%  [R0603]  51.48 135.18 90 top
R1249  1.82K_1%  [R0603]  45.51 126.42 0 top
R1250  X  [R0603]  60.88 138.61 180 bottom
R1251  X  [R0603]  85.77 139.5 90 bottom
R1252  X  [R0402]  47.67 145.97 90 top
R1253  4.7K  [R0402]  46.27 145.97 90 top
SINK1  FXW1126  [ZQ20100207_85M00X63M00X18M00]  90.85 80 90 top
SW1  -  [SWITCH_4]  201.34 72.44 90 top
SW2  -  [SWITCH_4]  201.34 63.42 90 top
U1  CDCV304PWR  [TSSOP_8]  154.1 101.4 270 top
U2  EPM1270F256C5N  [FBGA_256]  81.71 138.23 0 top
U3  TPS3823_33DBVRG4  [TPS3823]  95.93 137.72 180 top
U4  -  [46556-4145]  189.19 62.04 90 bottom
U5  TPS51200DRCR  [QFN_10_YEP2M40X1M65]  26.34 32.06 180 top
U6  TPS54327  [SOP_8_EP2M90X2M00]  136.57 158.17 270 top
U7  TPS53313  [QFN_24_EP2M45]  194.48 38.15 90 top
U8  TPS53313  [QFN_24_EP2M45]  185.72 158.29 180 top
U9  APL5915KAI_TRG  [SOP_8P]  158.54 156.39 270 top
U10  TPS54227  [SOP_8_EP2M90X2M00]  178.74 146.74 90 top
U11  TPS54227  [SOP_8_EP2M90X2M00]  178.48 136.32 90 top
U12  APL5915KAI_TRG  [SOP_8P]  131.62 60 270 top
U13  IRF7832TRPBFF  [SO_8]  129.33 147.5 270 top
U14  IRF7832TRPBFF  [SO_8]  88.44 120.96 270 top
U15  TPS54227  [SOP_8_EP2M90X2M00]  165.78 58.22 90 top
U16  APL5915KAI_TRG  [SOP_8P]  144.45 57.2 270 top
U17  TPS54327  [SOP_8_EP2M90X2M00]  167.43 68.12 90 top
U18  LM75AIM  [SO_8]  120.82 76 180 bottom
U19  AT24C02C_SSHM_T  [SOP_8]  131.62 99.49 270 top
U20  AST2500A2-GP  [BGA_465_1M46_RO014]  147.49 119.43 180 top
U21  MT40A256M16_083E  [FBGA_96_1M20_R14_GE]  154.22 140.64 270 top
U22  MX25L25635FMI-10G  [SO_16_2M65]  127.05 137.47 90 bottom
U23  MX25L25635FMI-10G  [SO_16_2M65]  127.05 137.34 270 top
U24  W25Q128FVSIG  [SOC_W_8]  127.05 137.47 0 bottom
U25  W25Q128FVSIG  [SOC_W_8]  127.05 137.47 0 top
U26  I210  [QFN_64_EP3M60]  169.21 114.1 90 bottom
U27  M25P16  [SOIC_8_2M50]  159.81 87.68 270 top
U29  TPS53622RSBT  [QFN_40_EPAD3M25]  121.97 22.53 0 top
U30  -  [CSD95490Q5MC]  111.17 18.09 180 top
U31  -  [CSD95490Q5MC]  99.23 18.09 180 top
U32  -  [CSD95492QVMT]  132.38 18.09 180 top
U33  TPS53622RSBT  [QFN_40_EPAD3M25]  168.83 36.12 0 top
U34  -  [CSD95492QVMT]  154.61 40.56 270 top
U35  -  [CSD95492QVMT]  154.61 49.96 270 top
U36  TPS53622RSBT  [QFN_40_EPAD3M25]  60.88 22.53 0 top
U37  -  [CSD95490Q5MC]  87.17 18.09 180 top
U38  -  [CSD95492QVMT]  75.48 18.09 180 top
U39  S25FL064P0XMFI001  [SO_16_2M65]  109.65 132.13 0 top
U40  W25Q128FVSIG  [SOC_W_8]  109.61 132.13 90 top
U41  S25FL064P0XMFI001  [SO_16_2M65]  109.65 144.96 0 top
U42  W25Q128FVSIG  [SOC_W_8]  109.23 144.96 90 top
U43  D-1527  [FCBGA_1667_3M556]  90.85 79.93 270 top
U44  M25P16  [SOIC_8_2M50]  149.27 71.04 180 bottom
U45  CDCV304PWR  [TSSOP_8]  123.62 127.18 270 top
U46  AT24C02C_SSHM_T  [SOP_8]  104.82 120.19 90 top
U47  74AVCH4T245PW  [TSSOP_16_1M10]  108.12 140.51 90 bottom
U48  74AVCH4T245PW  [TSSOP_16_1M10]  117.01 108.13 90 bottom
U49  74AVCH4T245PW  [TSSOP_16_1M10]  108 133.02 90 bottom
U50  74AVCH4T245PW  [TSSOP_16_1M10]  117.01 108.13 270 top
U51  74AVCH4T245PW  [TSSOP_16_1M10]  117.01 101.4 270 top
U52  74AVCH4T245PW  [TSSOP_16_1M10]  131.52 72.31 90 top
U53  LSF0108PWR  [TSSOP_20_PW]  131.52 72.31 90 bottom
U54  PCA9617ADP  [MSOP_8_1M1_2]  69.26 37.14 90 top
U55  74AVCH4T245PW  [TSSOP_16_1M10]  119.59 62.15 180 top
U56  PCA9617ADP  [MSOP_8_1M1_2]  131.28 104.78 270 top
U57  PCA9617ADP  [MSOP_8_1M1_2]  128.43 116.58 0 top
U58  74AVCH4T245PW  [TSSOP_16_1M10]  149.65 71.55 180 top
U59  74AVCH4T245PW  [TSSOP_16_1M10]  143.82 71.56 180 top
U60  -  [46556-4145]  199.29 143.69 270 bottom
U61  SN74CB3Q3384A  [TSSOP_24]  125.14 116.38 90 bottom
U62  SN74CB3Q3384A  [TSSOP_24]  87.3 155.88 180 bottom
U63  TPS54527  [SOP_8_EP2M90X2M00]  183.18 13.39 180 top
U64  APL5934KAI-TRG  [SOP_8P_EP3M50X3M00]  105.58 160.07 270 top
U65  APW7172KI_TRG  [SOP_8]  46.91 140.26 0 top
X1  M2STAND-OFF  [SCREW_HOLE_7M50X4M30_PST]  174.31 18.55 0 top
X2  M2STAND-OFF  [SCREW_HOLE_7M50X4M30_PST]  174.31 56.55 0 top
X3  -  [SCREW_N_M_3_5MM_1]  10 160 0 top
X4  -  [SCREW_N_M_3_5MM_1]  6 35 0 top
X5  -  [SCREW_N_M_3_5MM_1]  200 56.35 0 top
X6  -  [SCREW_N_M_3_5MM_1]  179.7 122.13 0 top
X7  -  [SCREW_N_M_3_5MM_1]  200 160 0 top
X8  -  [SCREW_N_M_3_5MM_1]  65 5 0 top
X11  -  [SCREW_N_M_3_5MM_1]  65 160 0 top
X12  -  [SCREW_N_M_3_5MM_1]  200 5 0 top
X13  -  [SCREW_N_M_3_5MM_1]  10 5 0 top
X16  -  [SCREW_NEW_M_3_3MM]  115 5 0 top
X17  -  [SCREW_NEW_M_3_3MM]  200 150 0 top
X18  -  [SCREW_NEW_M_3_3MM]  10 145 0 top
X19  -  [TEST_40]  17.95 33.71 0 top
X20  -  [TEST_40]  136.95 152.96 180 top
X21  -  [TEST_40]  193.59 56.82 0 top
X22  -  [TEST_40]  175.56 152.32 0 top
X23  -  [TEST_40]  152.95 150.17 0 top
X24  -  [TEST_40]  159.81 150.29 0 top
X25  -  [TEST_40]  167.18 131.62 0 top
X26  -  [TEST_40]  138.86 65.96 0 top
X27  -  [TEST_40]  146.48 62.41 0 top
X28  -  [TEST_40]  142.41 61.52 0 top
X29  -  [TEST_40]  155.24 76.51 0 top
X30  -  [TEST_40]  151.68 7.04 0 top
X32  -  [TEST_40]  151.68 3.99 0 top
X34  -  [TEST_40]  82.34 48.95 0 top
X35  -  [TEST_40]  58.72 34.98 0 top
X36  -  [TEST_40]  148.64 100.25 0 top
X37  -  [TEST_40]  70.66 141.91 0 top
X38  -  [TEST_40]  168.83 12.88 180 top
X39  -  [TEST_40]  99.87 150.8 270 top
Y1  32.768KHZ  [SMD_32768HZ]  97.71 112.45 90 top

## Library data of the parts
BZ1 = BATTERY
C1 C2 C55 C224 C225 C231-C236 C743 C745 = C0402: alternate symbols: (c0402;c0402_p;c0402_ap;C0402_PITCH0M8); signal model: DEFAULT_CAPACITOR_1.05e+014pF_2_1
C3-C12 C42 C256 C257 C263-C265 C564 C567-C569 = C0402_P: alternate symbols: (c0402;c0402_p); signal model: C0402_P_C0402_104_V-23030236-00_104
C13 = C0402: alternate symbols: (c0402;c0402_p;c0402_ap;C0402_PITCH0M8); signal model: DEFAULT_CAPACITOR_4.7pF_2_1
C14 C16 C18 C20 C71 C72 C75 C77 C81 C84 C85 C94 C105 C111 C124 C129 C134 C138 C140 C145 C146 C154 C157 C158 C166 C168 C171 C174 C178 C180 C183 C185 C189 C190 C197 C205 C207 C210 C214 C215 C223 C591 C593 = CAP_NP: signal model: DEFAULT_CAPACITOR_1.04e+014pF_2_1
C15 C23 C24 C28 C29 C73 C74 C80 = CAP_NP: signal model: DEFAULT_CAPACITOR_1.06e+014pF_2_1
C17 C56 C57 C226 C227 C260 C305 C758 = C0402_P: alternate symbols: (c0402;c0402_p)
C19 C592 = C0805: alternate symbols: (C0805;C0805_ap); signal model: DEFAULT_CAPACITOR_1.06e+014pF_2_1
C21 C22 C25-C27 C30-C41 C43 C238 C244 C246 C247 C254 C255 C259 C261 C262 C268-C271 C274-C277 C284-C287 C292-C294 C296 C298 C307 C319 C321 C324 C327 C613 C614 C679-C690 C693-C704 C759 C760 = C0402_P: alternate symbols: (c0402;c0402_p); signal model: DEFAULT_CAPACITOR_1.04e+014pF_2_1
C53 C54 C87 C228-C230 = C0402: alternate symbols: (c0402;c0402_p;c0402_ap;C0402_PITCH0M8); signal model: DEFAULT_CAPACITOR_1.04e+014pF_2_1
C58-C61 C252 C563 C566 C594 C730-C742 = C0402_P: alternate symbols: (c0402;c0402_p); signal model: C0402_P_C0402_103_V-23030019-00_103
C62-C69 C761-C763 C805 C816 C817 = C0402: alternate symbols: (c0402;c0402_p;c0402_ap;C0402_PITCH0M8)
C70 = CAP_NP: signal model: DEFAULT_CAPACITOR_4.7e+06pF_2_1
C76 C113 = CAP_NP: signal model: DEFAULT_CAPACITOR_1.02e+014pF_2_1
C78 C79 C368 C396 C412-C420 C445-C450 C465-C470 C491-C495 C502-C504 = C0805: alternate symbols: (C0805;C0805_ap); signal model: DEFAULT_CAPACITOR_2.2e+07pF_2_1
C82 C83 C91 C92 C101-C103 C106-C110 C121-C123 C135 C141 C143 C144 C151-C153 C155 C156 C163-C165 C172 C177 C181 C182 C186-C188 C195 C196 C198 C200 C201 C208 C212 C213 C221 C222 C342-C344 C348-C356 C359-C367 C370-C372 C376-C384 C387-C395 C398-C401 C404-C407 C409-C411 C434-C443 C457-C461 C463 C475-C477 C484-C486 C500 C501 C507 C508 C510 C515-C517 C606 C608 C634 C639 C640 C749-C752 C779 C780 = C0805: alternate symbols: (C0805;C0805_ap)
C86 C89 C93 C104 C120 C128 C131 C137 C147 C149 C159 C161 C175 C191 C193 C199 C216 C217 C524 C527 C781 C783-C787 C791-C804 C806 C807 C809-C813 C815 = CAP_NP
C88 C96 C97 C114 C115 C139 C148 C160 C176 C192 C202-C204 C206 C211 C218 = CAP_NP: signal model: DEFAULT_CAPACITOR_1.05e+014pF_2_1
C90 C95 C100 C112 C116 C119 C130 C150 C162 C194 C220 = CAP_NP: signal model: DEFAULT_CAPACITOR_1.03e+014pF_2_1
C98 C117 = CAP_NP: signal model: DEFAULT_CAPACITOR_220pF_2_1
C99 C118 = CAP_NP: signal model: DEFAULT_CAPACITOR_680pF_2_1
C125-C127 C133 C136 C142 C169 C170 C173 C209 C518-C521 = CAP_NP: signal model: DEFAULT_CAPACITOR_2.2e+07pF_2_1
C132 C167 = C0402: alternate symbols: (c0402;c0402_p;c0402_ap;C0402_PITCH0M8); signal model: DEFAULT_CAPACITOR_180pF_2_1
C179 C184 = C0402: alternate symbols: (c0402;c0402_p;c0402_ap;C0402_PITCH0M8); signal model: C0402_P_C0402_104_V-23030236-00_104
C219 C315 C347 C375 C402 C432 C455 C464 C488 C499 C615-C632 C638 C641 C658 C674-C678 C729 C757 C764 C765 C788-C790 = C0603: alternate symbols: (C0603;C0603_ap)
C237 C239-C243 C245 C248-C250 C258 C314 C570-C577 C602 C633 C746-C748 C767-C778 = C0402: alternate symbols: (c0402;c0402_p;c0402_ap)
C251 = C0402: alternate symbols: (c0402;c0402_p;c0402_ap); signal model: DEFAULT_CAPACITOR_100pF_2_1
C253 C290 C291 C295 C297 C299-C304 C308-C313 C316 C318 C320 C323 C326 = C0402_P: alternate symbols: (c0402;c0402_p); signal model: DEFAULT_CAPACITOR_1.05e+014pF_2_1
C266 C267 C272 C273 C278 C279 C282 C283 = CAP_NP: signal model: DEFAULT_CAPACITOR_1e+07pF_2_1
C280 C281 = C0402_P: alternate symbols: (c0402;c0402_p); signal model: DEFAULT_CAPACITOR_27pF_2_1
C288 = C0402: alternate symbols: (c0402;c0402_p;c0402_ap); signal model: DEFAULT_CAPACITOR_22000pF_2_1
C289 = C0402: alternate symbols: (c0402;c0402_p;c0402_ap); signal model: DEFAULT_CAPACITOR_18000pF_2_1
C306 C317 C322 C325 C328 = C0402_P: alternate symbols: (c0402;c0402_p); signal model: DEFAULT_CAPACITOR_100pF_2_1
C335 C340 C426 C431 C478 C483 C506 C562 C565 C597-C601 C605 C607 C635-C637 C642-C644 C649-C654 C659-C672 = C0402: alternate symbols: (c0402;c0402_p;c0402_ap); signal model: DEFAULT_CAPACITOR_1.05e+014pF_2_1
C336 C358 C386 C425 C427 C454 C474 C479 C497 C514 = C0402: alternate symbols: (c0402;c0402_p;c0402_ap); signal model: DEFAULT_CAPACITOR_1.02e+014pF_2_1
C337 C428 C480 = C0805: alternate symbols: (C0805;C0805_ap); signal model: DEFAULT_CAPACITOR_1.05e+014pF_2_1
C338 C429 C481 = C0603: alternate symbols: (C0603;C0603_ap); signal model: DEFAULT_CAPACITOR_2200pF_2_1
C339 C341 C346 C369 C374 C397 C422 C424 C430 C451 C453 C471 C473 C482 C489 C498 C511 C513 C578-C581 C584 C585 C595 C596 C645-C648 C655 C656 C673 C691 C692 = C0402: alternate symbols: (c0402;c0402_p;c0402_ap); signal model: DEFAULT_CAPACITOR_1.04e+014pF_2_1
C345 C373 C487 = C0603: alternate symbols: (C0603;C0603_ap); signal model: DEFAULT_CAPACITOR_4700pF_2_1
C357 C385 C423 C452 C472 C496 C512 = C0603: alternate symbols: (C0603;C0603_ap); signal model: DEFAULT_CAPACITOR_2.2e+06pF_2_1
C403 C433 C456 C490 C753 C756 C808 C814 = C1206: alternate symbols: (C1206;C1206_ap)
C408 C444 C462 C509 = C0603: alternate symbols: (C0603;C0603_ap); signal model: DEFAULT_CAPACITOR_3300pF_2_1
C421 = C0805: alternate symbols: (C0805;C0805_ap); signal model: DEFAULT_CAPACITOR_2.2e+06pF_2_1
C528 C550 = C0402: alternate symbols: (c0402;c0402_p;c0402_ap;C0402_PITCH0M8); signal model: DEFAULT_CAPACITOR_1.03e+014pF_2_1
C582 C583 C589 C590 = C0402: alternate symbols: (c0402;c0402_p;c0402_ap); signal model: DEFAULT_CAPACITOR_27pF_2_1
C586 = C0201: alternate symbols: (C0201;C0201_AP); signal model: DEFAULT_CAPACITOR_10pF_2_1
C587 C588 = C0603: alternate symbols: (C0603;C0603_ap); signal model: DEFAULT_CAPACITOR_18pF_2_1
C603 = C0603: alternate symbols: (C0603;C0603_ap); signal model: DEFAULT_CAPACITOR_1.04e+014pF_2_1
C604 = C0603: alternate symbols: (C0603;C0603_ap); signal model: DEFAULT_CAPACITOR_1.03e+014pF_2_1
C657 = C0402: alternate symbols: (c0402;c0402_p;c0402_ap); signal model: DEFAULT_CAPACITOR_1.03e+014pF_2_1
C713-C728 = C0402: alternate symbols: (c0402;c0402_p;c0402_ap); signal model: C0402_C0402_220NF/16V_V-2303027_220nF/16V
C744 = C0402_P: alternate symbols: (c0402;c0402_p); signal model: DEFAULT_CAPACITOR_1.03e+014pF_2_1
CD1-CD4 CD6 CD8 CD9 CD12-CD14 CD16-CD18 CD20 = CAP_POL
CD7 CD10 CD11 CD19 = CDNCC_0810_AP: alternate symbols: (CDNCC_0810;CDNCC_0810_AP)
COUPON1-COUPON4 = COUPON
D1-D18 D20 D30 = LED_2P
D21 = BAT54CLT1
D31 D32 = DIODE
FD1 FD3-FD6 FD10-FD14 = MARK
J1 J5 = JP_10
J3 = 10131758
J4 = HX42003_4
J7 = 10141732
J8 = 10141997
JP1 JP2 = JP_3P
L1-L6 L8-L13 L15-L22 L28 L31 L35 L37 = Inductor
L7 L14 = MWSA0603S-3R3MT
L23-L26 L29 L30 L36 = L_7M2X6M5X3_AP: alternate symbols: (L_7M2X6M5X3;L_7M2X6M5X3_AP)
L27 = L1206: alternate symbols: (L1206;L1206_AP)
L32 L33 = L0603: alternate symbols: (L0603;L0603_AP)
OSC1 OSC6 = OSC_SQR
OSC2 = D3SX24E000008E
OSC3-OSC5 = 7M20000025
Q1 Q4 = SM12
Q2 Q3 Q5 Q6 Q35 Q36 = APM1105NUC_TRG_1
Q7-Q9 Q14 = BCE_PNP_1_AP: alternate symbols: (SOT_23;SOT_23_AP)
Q10 Q11 Q15-Q30 Q33 Q34 Q37 Q38 = BCE_NPN
Q39 Q41 = BCE_NPN_AP: alternate symbols: (SOT_23;SOT_23_AP)
Q40 = APL431LAAC_TRG_AP: alternate symbols: (SOT_23;SOT_23_AP)
R1 R7 R105 R108 R119 R120 R122 R123 R125 R126 R137 R138 R164 R167 R168 R241 R250 R258 R265 R271-R273 R276 R282-R284 R294 R302 R310 R314-R316 R868 R871 R888 R897 R917 R976 R1028 = R0402: alternate symbols: (r0402,r0402_p,R0402_AP); signal model: DEFAULT_RESISTOR_1000OHM_2_1
R2 R8 R10 R194 R196 R199 R551 = R0402: alternate symbols: (r0402,r0402_p,R0402_AP); signal model: DEFAULT_RESISTOR_560OHM_2_1
R3 R6 R9 R48-R50 R52 R53 R60 R61 R63 R65-R67 R81 R98 R115 R616 R618-R620 R839 R849 R852 R853 R1142 R1167-R1170 = R0402: alternate symbols: (r0402,r0402_p,R0402_AP); signal model: R0402_R0402_33_V-21010237-000_R_33
R4 R5 R21-R25 R31-R33 R35 R36 R42-R45 R70 R73 R75-R78 R94 R95 R109-R111 R229 R275 R286 R288 R292 R296 R298 R301 R311 R312 R317 R334-R339 R341-R343 R379-R402 R404 R405 R407-R428 R600 R601 R610 R611 R630 R632 R644 R650-R654 R657 R664 R689 R696-R698 R700 R702 R725 R727 R733-R735 R737 R740 R781 R782 R784-R787 R792-R799 R816-R824 R827 R830-R836 R838 R842-R845 R847 R848 R850 R851 R854-R859 R861 R862 R864 R865 R870 R873 R874 R876 R877 R879 R880 R882-R886 R891 R892 R895 R896 R898-R901 R908 R910-R913 R918 R920-R933 R936 R937 R945-R956 R958 R961-R966 R968-R970 R972 R974 R975 R977 R978 R983-R990 R992-R996 R1018-R1020 R1023 R1025 R1039 R1063 R1076 R1077 R1164 R1165 R1172 R1173 R1175 R1176 R1188-R1191 R1195 R1199 R1200 R1202 R1203 R1206-R1212 R1216-R1218 R1221 R1222 R1239 R1240 R1245 R1246 R1252 R1253 = R0402: alternate symbols: (r0402,r0402_p,R0402_AP)
R11 R12 R57 R521-R523 R938 = R0402: alternate symbols: (r0402,r0402_p,R0402_AP); signal model: DEFAULT_RESISTOR_22OHM_2_1
R13 R14 R465 R760-R762 R770-R772 R802 R805 R806 R1053 R1093 R1094 R1097 R1098 R1143-R1146 R1157-R1162 R1184 = R0402: alternate symbols: (r0402,r0402_p,R0402_AP); signal model: DEFAULT_RESISTOR_4700OHM_2_1
R15-R18 R118 R121 R124 R166 = R0402: alternate symbols: (r0402,r0402_p,R0402_AP); signal model: DEFAULT_RESISTOR_330OHM_2_1
R19 R20 R51 R59 R64 R72 R74 R79 R80 R82 R83 R85-R93 R127 R129 R131 R139 R140 R142 R145-R152 R165 R169-R184 R186-R190 R192 R193 R195 R197 R198 R205 R208 R214 R234 R242 R252 R287 R303 R313 R347 R348 R352 R353 R356 R357 R360 R361 R364 R365 R369-R372 R374 R376 R377 R436 R437 R444 R445 R455-R457 R459-R463 R535 R536 R592 R596 R641-R643 R647 R648 R656 R658-R660 R666 R669 R670 R673 R676 R677 R679 R682 R684-R688 R693 R694 R703-R706 R709 R712 R714 R716 R719 R721 R722 R724 R726 R730 R731 R739 R741-R743 R746 R750 R751 R754 R757 R759 R811-R815 R829 R841 R863 R869 R875 R881 R905 R916 R919 R934 R935 R973 R991 R1115 R1129-R1133 R1163 = R0402: alternate symbols: (r0402,r0402_p,R0402_AP); signal model: R0402_R0402_0_V-21010235-000_R0_0
R26-R30 R37-R41 R480-R482 R486 R488 R492-R495 R498 R513-R518 R538 R539 R1040-R1043 R1045-R1047 R1049 R1050 R1059-R1062 R1064 R1068-R1071 R1107 R1109 R1110 R1112 = R0402_P: alternate symbols: (r0402;r0402_p); signal model: DEFAULT_RESISTOR_0.001OHM_2_1
R34 R226 R566 R568 R570 R572 R573 R575 R577 R578 R581 R584 R586 R588 R591 = R0402: alternate symbols: (r0402,r0402_p,R0402_AP); signal model: R0402_R0402_3.3K_1%_V-21010428-_3.3K_1%
R46 R47 R71 R112 R163 R201 R204 R318 R320 R322 R323 R340 R344 R373 R375 R403 R406 R438-R440 R442 R490 R491 R496 R497 R499-R502 R527 R529-R532 R541-R547 R553 R561-R565 R567 R569 R571 R574 R576 R579 R580 R582 R583 R585 R587 R589 R590 R593 R594 R603-R606 R609 R663 R671 R683 R690 R699 R713 R720 R728 R736 R752 R758 R825 R826 R837 R860 R866 R867 R872 R878 R887 R889 R902-R904 R957 R1056 R1079 R1080 R1083 R1085 R1086 R1116 R1118 R1120 R1122 R1123 R1125 R1134-R1136 R1174 R1180 = R0402: alternate symbols: (r0402,r0402_p,R0402_AP); signal model: R0402_R0402_X_R0402_R0402_P_R04_X
R54 R56 R58 R331 R332 R431 R432 R434 R435 R763 R765-R769 R773 R774 R776-R779 R803 R804 R807 R808 R940 R942-R944 R1005 R1006 R1111 = R0402_P: alternate symbols: (r0402;r0402_p); signal model: R0402_P_R0402_33_V-21010237-000_33
R55 R68 R69 R106 R107 R133 R134 R238 R244 R253 R263 R266-R268 R274 R277 R279 R280 R285 R289 R300 R305 R319 R321 R324 R325 R329 R330 R333 R441 R443 R467 R468 R470 R472 R473 R475 R503-R512 R524-R526 R528 R533 R534 R554-R560 R628 R941 R997-R1000 = R0402_P: alternate symbols: (r0402;r0402_p); signal model: DEFAULT_RESISTOR_4700OHM_2_1
R84 R1003 R1138 = R0402: alternate symbols: (r0402,r0402_p,R0402_AP); signal model: DEFAULT_RESISTOR_0.001OHM_2_1
R96 R97 R99-R104 = R0402_P: alternate symbols: (r0402;r0402_p); signal model: DEFAULT_RESISTOR_560OHM_2_1
R113 R615 = R0402_P: alternate symbols: (r0402;r0402_p); signal model: DEFAULT_RESISTOR_22OHM_2_1
R114 R116 R117 R1139-R1141 = R0402: alternate symbols: (r0402,r0402_p,R0402_AP); signal model: DEFAULT_RESISTOR_100OHM_2_1
R159-R162 = R0603: alternate symbols: (R0603,R0603_AP); signal model: DEFAULT_RESISTOR_0.001OHM_2_1
R185 R191 R213 R220 R225 R235 R237 R245 R247 R251 R255 R262 R269 R278 R290 R291 R299 R306 R307 R537 R552 R595 R597-R599 R627 R1087 R1095 R1103 R1104 = R0402_P: alternate symbols: (r0402;r0402_p); signal model: R0402_P_R0402_10K_1%_V-21010229_10K_1%
R200 = R0805: alternate symbols: (R0805,R0805_AP); signal model: DEFAULT_RESISTOR_0.001OHM_2_1
R202 R203 R206 R207 R209 R212 R215 R216 R222 R227 R231 R233 R236 R239 R240 R248 R249 R257 R259-R261 R264 R293 R295 R297 R309 R349 R617 R631 R1214 R1232 R1233 R1236-R1238 = RESISTOR
R210 R211 R217 R219 R254 R256 R304 R308 R645 R646 R649 R668 R675 R681 R691 R692 R695 R711 R718 R729 R732 R749 R756 R810 R890 R894 R939 R967 R1166 R1192-R1194 R1196-R1198 R1213 R1215 R1241-R1244 R1247-R1251 = R0603: alternate symbols: (R0603,R0603_AP)
R218 R228 = RESISTOR: signal model: DEFAULT_RESISTOR_300OHM_2_1
R221 R230 = RESISTOR: signal model: DEFAULT_RESISTOR_10000OHM_2_1
R223 R232 R629 = RESISTOR: signal model: DEFAULT_RESISTOR_0.001OHM_2_1
R224 = RESISTOR: signal model: DEFAULT_RESISTOR_1OHM_2_1
R243 R246 R667 R674 R678 R708 R715 R748 R753 R959 = R0805: alternate symbols: (R0805,R0805_AP)
R270 R281 R788 R789 R791 R1088-R1090 = R0402: alternate symbols: (r0402,r0402_p,R0402_AP); signal model: DEFAULT_RESISTOR_10OHM_2_1
R326-R328 R429 R458 R602 R607 R608 R621-R626 R764 R775 R780 R783 R790 R800 R801 R828 R906 R907 R909 R914 R915 R982 R1001 R1002 R1004 R1007 R1037 R1048 R1054 R1055 R1058 R1091 R1092 R1099-R1102 R1137 R1177-R1179 R1181-R1183 R1186 R1187 R1204 R1205 R1219 R1220 R1230 R1231 R1234 R1235 = R0402_P: alternate symbols: (r0402;r0402_p)
R345 R346 R350 R351 R354 R355 R358 R359 R362 R363 R366 R367 = R0402_P: alternate symbols: (r0402;r0402_p); signal model: DEFAULT_RESISTOR_100OHM_2_1
R368 = R0603: alternate symbols: (R0603,R0603_AP); signal model: R0402_R0402_0_V-21010235-000_R0_0
R378 R483-R485 R487 R489 R519 R520 R840 R893 = R0402: alternate symbols: (r0402,r0402_p,R0402_AP); signal model: DEFAULT_RESISTOR_2200OHM_2_1
R430 R433 = R0402: alternate symbols: (r0402,r0402_p,R0402_AP); signal model: R0402_R0402_60.4_1%_V-21010497-_60.4_1%
R454 R464 R979-R981 R1030-R1036 R1051 R1052 R1057 R1065 R1066 R1072-R1075 R1078 R1081 R1082 R1096 R1105 R1106 R1108 R1113 R1114 = R0402_P: alternate symbols: (r0402;r0402_p); signal model: DEFAULT_RESISTOR_1000OHM_2_1
R548 R549 R960 = R0402: alternate symbols: (r0402,r0402_p,R0402_AP); signal model: DEFAULT_RESISTOR_8200OHM_2_1
R550 = R0402_P: alternate symbols: (r0402;r0402_p); signal model: DEFAULT_RESISTOR_10OHM_2_1
R612-R614 R1185 = R0402: alternate symbols: (r0402,r0402_p,R0402_AP); signal model: R0402_R0402_33_1%_V-21010461-00_33_1%
R662 = R0402: alternate symbols: (r0402,r0402_p,R0402_AP); signal model: DEFAULT_RESISTOR_56OHM_2_1
R665 R672 R680 R710 R717 R745 R755 = R0603: alternate symbols: (R0603,R0603_AP); signal model: DEFAULT_RESISTOR_2OHM_2_1
R723 = R0402: alternate symbols: (r0402,r0402_p,R0402_AP); signal model: DEFAULT_RESISTOR_3.3OHM_2_1
R809 R846 R971 = R0603: alternate symbols: (R0603,R0603_AP); signal model: DEFAULT_RESISTOR_7500OHM_2_1
R1008 = R1206: alternate symbols: (R1206,R1206_AP); signal model: DEFAULT_RESISTOR_0.001OHM_2_1
R1029 = R0402_P: alternate symbols: (r0402;r0402_p); signal model: DEFAULT_RESISTOR_150OHM_2_1
R1084 = R0603: alternate symbols: (R0603,R0603_AP); signal model: DEFAULT_RESISTOR_200000OHM_2_1
SINK1 = FXW1126
SW1 SW2 = SWITCH_4
U1 U45 = CDCV304PWR
U2 = EPM1270F256C5N
U3 = TPS3823_33DBVRG4
U4 U60 = 46556-4145
U5 = TPS51200DRCR
U6 U10 U11 U15 U17 U63 = TPS54227
U7 U8 = TPS53313
U9 U12 U16 = APL5915KAI_TRG
U13 U14 = IRF7832TRPBFF
U18 = LM75A
U19 U46 = 24C02
U20 = AST2500A2-GP
U21 = MT40A256M16_083E
U22 U23 = MX25L25635FMI-10G
U24 U25 U40 U42 = W25Q128FVSIG
U26 = I210
U27 U44 = M25P16
U29 U33 U36 = TPS53622RSBT
U30 U31 U37 = CSD95490Q5MC
U32 U34 U35 U38 = CSD95492QVMT
U39 U41 = S25FL064P0XMFI001
U43 = D-1527
U47-U52 U55 U58 U59 = 74AVCH4T245PW
U53 = LSF0108PWR
U54 U56 U57 = PCA9617ADP
U61 U62 = SN74CB3Q3384A
U64 = APL5934KAI-TRG
U65 = APW7172KI_TRG_0
X1 X2 = M2STAND-OFF
X3-X8 X11-X13 = SCREW_N
X16-X18 = SCREW_NEW
X19-X30 X32 X34-X39 = TEST_40
Y1 = MC306

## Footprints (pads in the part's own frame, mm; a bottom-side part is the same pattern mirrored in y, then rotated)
1125_1205G0M110P1
  rect 1.02x3.12 smd: 1(-5.08,-2.69) 2(-5.08,2.69) 3(-2.54,-2.69) 4(-2.54,2.69) 5(0,-2.69) 6(0,2.69) 7(2.54,-2.69) 8(2.54,2.69) 9(5.08,-2.69) 10(5.08,2.69)
46556-4145
  round 1.27 hole 1.27 unplated: (0,0) (54.39,2.01)
  round 0.635 smd: A1(2.43,-1.9) A2(3.7,-1.9) A3(4.97,-1.9) A4(6.24,-1.9) A5(7.51,-1.9) A6(8.78,-1.9) A7(10.05,-1.9) A8(11.32,-1.9) A9(12.59,-1.9) A10(13.86,-1.9) A11(15.13,-1.9) A12(16.4,-1.9) A13(17.67,-1.9) A14(18.94,-1.9) A15(20.21,-1.9) A16(21.48,-1.9) A17(22.75,-1.9) A18(24.02,-1.9) A19(25.29,-1.9) A20(26.56,-1.9) A21(27.83,-1.9) A22(29.1,-1.9) A23(30.37,-1.9) A24(31.64,-1.9) A25(32.91,-1.9) A26(34.18,-1.9) A27(35.45,-1.9) A28(36.72,-1.9) A29(37.99,-1.9) A30(39.26,-1.9) A31(40.53,-1.9) A32(41.8,-1.9) A33(43.07,-1.9) A34(44.34,-1.9) A35(45.61,-1.9) A36(46.88,-1.9) A37(48.15,-1.9) A38(49.42,-1.9) A39(50.69,-1.9) A40(51.96,-1.9) B1(2.43,-0.63) B2(3.7,-0.63) B3(4.97,-0.63) B4(6.24,-0.63) B5(7.51,-0.63) B6(8.78,-0.63) B7(10.05,-0.63) B8(11.32,-0.63) B9(12.59,-0.63) B10(13.86,-0.63) B11(15.13,-0.63) B12(16.4,-0.63) B13(17.67,-0.63) B14(18.94,-0.63) B15(20.21,-0.63) B16(21.48,-0.63) B17(22.75,-0.63) B18(24.02,-0.63) B19(25.29,-0.63) B20(26.56,-0.63) B21(27.83,-0.63) B22(29.1,-0.63) B23(30.37,-0.63) B24(31.64,-0.63) B25(32.91,-0.63) B26(34.18,-0.63) B27(35.45,-0.63) B28(36.72,-0.63) B29(37.99,-0.63) B30(39.26,-0.63) B31(40.53,-0.63) B32(41.8,-0.63) B33(43.07,-0.63) B34(44.34,-0.63) B35(45.61,-0.63) B36(46.88,-0.63) B37(48.15,-0.63) B38(49.42,-0.63) B39(50.69,-0.63) B40(51.96,-0.63) C1(2.43,0.64) C2(3.7,0.64) C3(4.97,0.64) C4(6.24,0.64) C5(7.51,0.64) C6(8.78,0.64) C7(10.05,0.64) C8(11.32,0.64) C9(12.59,0.64) C10(13.86,0.64) C11(15.13,0.64) C12(16.4,0.64) C13(17.67,0.64) C14(18.94,0.64) C15(20.21,0.64) C16(21.48,0.64) C17(22.75,0.64) C18(24.02,0.64) C19(25.29,0.64) C20(26.56,0.64) C21(27.83,0.64) C22(29.1,0.64) C23(30.37,0.64) C24(31.64,0.64) C25(32.91,0.64) C26(34.18,0.64) C27(35.45,0.64) C28(36.72,0.64) C29(37.99,0.64) C30(39.26,0.64) C31(40.53,0.64) C32(41.8,0.64) C33(43.07,0.64) C34(44.34,0.64) C35(45.61,0.64) C36(46.88,0.64) C37(48.15,0.64) C38(49.42,0.64) C39(50.69,0.64) C40(51.96,0.64) D1(2.43,1.91) D2(3.7,1.91) D3(4.97,1.91) D4(6.24,1.91) D5(7.51,1.91) D6(8.78,1.91) D7(10.05,1.91) D8(11.32,1.91) D9(12.59,1.91) D10(13.86,1.91) D11(15.13,1.91) D12(16.4,1.91) D13(17.67,1.91) D14(18.94,1.91) D15(20.21,1.91) D16(21.48,1.91) D17(22.75,1.91) D18(24.02,1.91) D19(25.29,1.91) D20(26.56,1.91) D21(27.83,1.91) D22(29.1,1.91) D23(30.37,1.91) D24(31.64,1.91) D25(32.91,1.91) D26(34.18,1.91) D27(35.45,1.91) D28(36.72,1.91) D29(37.99,1.91) D30(39.26,1.91) D31(40.53,1.91) D32(41.8,1.91) D33(43.07,1.91) D34(44.34,1.91) D35(45.61,1.91) D36(46.88,1.91) D37(48.15,1.91) D38(49.42,1.91) D39(50.69,1.91) D40(51.96,1.91)
